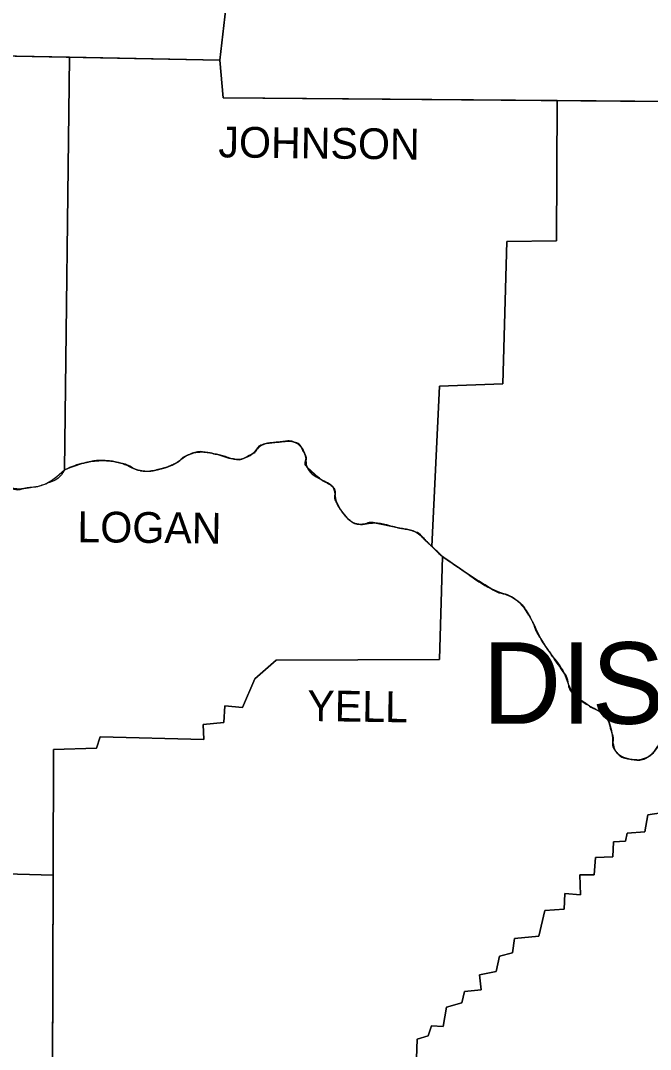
# Model space of a CAD drawing. Extents: x 1368042 to 1371376, y 380392 to 382637.
# Drawn here: x 1369334.7 to 1369518.4, y 381224.9 to 381525.2 of the extents above; entities that cross this region are included whole.
import ezdxf

# ---------------------------------------------------------------- set-up
doc = ezdxf.new("R2010")
doc.units = 0
doc.layers.add('Default', color=7, linetype='Continuous')
doc.layers.add('R_No Plot', color=7, linetype='Continuous')

msp = doc.modelspace()

# ---------------------------------------------------------------- linework, layer by layer
at = {"layer": 'Default'}
for points in [[(1369128.89, 381624.79), (1369168.7, 381624.58), (1369169.75, 381638.36), (1369184.15, 381638.36), (1369185.41, 381660.71), (1369266.85, 381657.78), (1369269.35, 381664.05), (1369302.97, 381664.26), (1369286.06, 381615.81), (1369282.72, 381538.34), (1369280.21, 381538.13), (1369278.96, 381514.74), (1369291.28, 381513.7), (1369293.16, 381515.58), (1369392.77, 381513.7), (1369393.81, 381502.63)], [(1369404.64, 381627.34), (1369405.51, 381615.6), (1369415.11, 381614.98), (1369412.61, 381579.89), (1369408.22, 381580.1), (1369407.39, 381574.47), (1369402.37, 381574.47), (1369402.17, 381564.86), (1369399.03, 381564.65), (1369397.99, 381552.33), (1369393.4, 381551.7), (1369392.77, 381532.91), (1369394.86, 381531.45), (1369392.77, 381513.7)], [(1369393.81, 381502.63), (1369625.61, 381500.75), (1369626.65, 381522.68), (1369681.07, 381522.05)], [(1369348.92, 381514.53), (1369347.45, 381394.05)], [(1369491.19, 381501.84), (1369490.97, 381460.94), (1369476.56, 381460.73), (1369475.31, 381419.17), (1369456.93, 381418.54), (1369454.66, 381371.69)], [(1369320.52, 381400.73), (1369319.05, 381370.87), (1369291.91, 381370.66), (1369290.45, 381343.51), (1369263.51, 381344.14), (1369262.67, 381316.16), (1369234.48, 381315.95), (1369233.65, 381287.97), (1369251.4, 381286.92), (1369250.77, 381278.36), (1369344.2, 381275.78)], [(1369457.71, 381368.78), (1369456.88, 381338.71), (1369409.27, 381338.5), (1369403, 381333.07), (1369399.45, 381324.72), (1369394.23, 381325.14), (1369394.02, 381320.33), (1369387.97, 381319.71), (1369388.18, 381315.32), (1369357.9, 381316.16), (1369356.85, 381312.82), (1369344.32, 381312.4), (1369344.2, 381275.78)], [(1369522.24, 381294.02), (1369517.65, 381293.4), (1369516.81, 381288.38), (1369511.59, 381287.97), (1369511.17, 381285.67), (1369507.62, 381285.46), (1369507.41, 381281.08), (1369502.4, 381280.87), (1369501.98, 381275.85), (1369497.81, 381275.85), (1369498.02, 381270.01), (1369493.42, 381270.43), (1369493.21, 381265.83), (1369487.58, 381265.41), (1369485.9, 381257.9), (1369478.8, 381257.27), (1369478.18, 381253.09), (1369474.42, 381252.05), (1369473.38, 381247.66), (1369468.57, 381246.62), (1369468.99, 381242.24), (1369464.19, 381241.82), (1369463.35, 381238.48), (1369458.97, 381237.22), (1369457.92, 381231.59), (1369454.58, 381231.79), (1369453.54, 381228.87), (1369450.4, 381227.83), (1369450.2, 381222.19)], [(1369344.2, 381275.78), (1369343.9, 381190.24), (1369333.46, 381190.03), (1369334.3, 381183.77), (1369324.27, 381183.97), (1369324.07, 381179.38), (1369314.25, 381179.38), (1369314.46, 381176.04), (1369299.84, 381175.62), (1369299.63, 381162.88), (1369285.43, 381164.14), (1369283.14, 381061.4), (1369202.74, 381061.61), (1369200.86, 381037.8), (1369203.78, 381035.71), (1369203.57, 381008.98), (1369143.36, 381011.63)]]:
    msp.add_lwpolyline(points, dxfattribs=at)
for points in [[(1369347.45, 381394.05), (1369354.35, 381396.34), (1369359.36, 381396.76), (1369364.37, 381395.93), (1369369.59, 381393.84), (1369375.23, 381394.26), (1369379.4, 381395.72), (1369383.58, 381398.43), (1369388.18, 381399.27), (1369392.56, 381398.43), (1369397.15, 381397.18), (1369402.17, 381398.64), (1369405.09, 381401.35), (1369410.1, 381402.19), (1369414.49, 381402.19), (1369417.62, 381398.64), (1369418.25, 381394.88), (1369422.21, 381391.33), (1369425.76, 381389.03), (1369426.81, 381384.65), (1369428.69, 381381.52), (1369430.57, 381379.43), (1369433.28, 381378.18), (1369437.88, 381378.59), (1369444.98, 381377.13), (1369449.57, 381376.09), (1369453.75, 381372.54), (1369457.71, 381368.78)], [(1369320.52, 381400.73), (1369325.11, 381397.81), (1369328.66, 381393), (1369331.79, 381389.03), (1369337.01, 381388.83), (1369341.19, 381389.66), (1369347.45, 381394.05)], [(1369457.71, 381368.78), (1369465.02, 381363.77), (1369471.91, 381359.38), (1369479.01, 381356.25), (1369482.98, 381351.66), (1369486.53, 381344.56), (1369489.45, 381340.17), (1369493.21, 381334.74), (1369495.93, 381328.69), (1369500.31, 381325.34), (1369504.91, 381322.42), (1369507.2, 381317.2), (1369508.25, 381311.98), (1369513.26, 381309.47), (1369518.06, 381310.52), (1369520.78, 381313.65), (1369523.28, 381319.08), (1369528.92, 381320.75), (1369536.23, 381321.38), (1369544.58, 381323.26), (1369553.77, 381322.84), (1369566.72, 381322)]]:
    msp.add_spline(points, degree=3, dxfattribs=at)
at = {"layer": 'R_No Plot'}
for p, q in [((1369347.45, 381394.05), (1369348.92, 381514.53)), ((1369348.92, 381514.53), (1369347.45, 381394.05)), ((1369348.92, 381514.53), (1369348.92, 381514.53)), ((1369348.92, 381514.53), (1369392.77, 381513.7)), ((1369392.77, 381513.7), (1369348.92, 381514.53)), ((1369392.77, 381513.7), (1369393.81, 381502.63)), ((1369393.81, 381502.63), (1369392.77, 381513.7)), ((1369393.81, 381502.63), (1369543.11, 381501.42)), ((1369491.19, 381501.84), (1369393.81, 381502.63)), ((1369491.19, 381501.84), (1369490.97, 381460.94)), ((1369543.11, 381501.42), (1369491.19, 381501.84)), ((1369476.56, 381460.73), (1369475.31, 381419.17)), ((1369490.97, 381460.94), (1369476.56, 381460.73)), ((1369456.93, 381418.54), (1369454.66, 381371.69)), ((1369475.31, 381419.17), (1369456.93, 381418.54)), ((1369387.98, 381399.29), (1369388.18, 381399.27)), ((1369368.84, 381394.03), (1369369.59, 381393.84)), ((1369418.25, 381394.88), (1369421.72, 381391.72)), ((1369430.57, 381379.43), (1369430.57, 381379.43)), ((1369433.28, 381378.18), (1369435.57, 381378.4)), ((1369437.88, 381378.59), (1369444.6, 381377.21)), ((1369482.98, 381351.66), (1369481.45, 381353.93)), ((1369394.23, 381325.14), (1369394.02, 381320.33)), ((1369504.91, 381322.42), (1369504.7, 381322.62)), ((1369394.02, 381320.33), (1369387.97, 381319.71)), ((1369357.9, 381316.16), (1369356.85, 381312.82)), ((1369344.32, 381312.4), (1369344.2, 381275.78)), ((1369356.85, 381312.82), (1369344.32, 381312.4)), ((1369344.2, 381275.78), (1369343.9, 381190.24)), ((1369493.42, 381270.43), (1369493.21, 381265.83)), ((1369498.02, 381270.01), (1369493.42, 381270.43)), ((1369468.57, 381246.62), (1369468.99, 381242.24)), ((1369464.19, 381241.82), (1369463.35, 381238.48)), ((1369468.99, 381242.24), (1369464.19, 381241.82))]:
    msp.add_line(p, q, dxfattribs=at)
for points in [[(1369302.97, 381664.26), (1369286.06, 381615.81), (1369282.72, 381538.34), (1369280.21, 381538.13), (1369278.99, 381515.39), (1369278.96, 381514.74), (1369291.28, 381513.7), (1369293.16, 381515.58), (1369348.92, 381514.53)], [(1369404.64, 381627.34), (1369405.51, 381615.6), (1369415.11, 381614.98), (1369412.61, 381579.89), (1369408.22, 381580.1), (1369407.39, 381574.47), (1369402.37, 381574.47), (1369402.17, 381564.86), (1369399.03, 381564.65), (1369397.99, 381552.33), (1369393.4, 381551.7), (1369392.77, 381532.91), (1369394.86, 381531.45), (1369392.77, 381513.7)], [(1369392.77, 381513.7), (1369394.86, 381531.45), (1369392.77, 381532.91), (1369393.4, 381551.7)], [(1369348.92, 381514.53), (1369348.92, 381514.53), (1369297.34, 381515.5)], [(1369348.92, 381514.53), (1369348.92, 381514.53)], [(1369454.66, 381371.69), (1369456.93, 381418.54), (1369475.31, 381419.17), (1369476.56, 381460.73), (1369490.97, 381460.94), (1369491.19, 381501.84)], [(1369454.66, 381371.69), (1369454.66, 381371.69)], [(1369344.2, 381275.78), (1369344.32, 381312.4), (1369356.85, 381312.82), (1369357.9, 381316.16), (1369388.18, 381315.32), (1369387.97, 381319.71), (1369394.02, 381320.33), (1369394.23, 381325.14), (1369399.45, 381324.72), (1369403, 381333.07), (1369409.27, 381338.5), (1369456.88, 381338.71), (1369457.71, 381368.78)], [(1369457.71, 381368.78), (1369456.88, 381338.71), (1369409.27, 381338.5), (1369403, 381333.07)], [(1369263.33, 381338.19), (1369262.67, 381316.16), (1369234.48, 381315.95), (1369233.65, 381287.97), (1369251.4, 381286.92), (1369250.77, 381278.36), (1369344.2, 381275.78)], [(1369403, 381333.07), (1369399.45, 381324.72), (1369394.23, 381325.14)], [(1369387.97, 381319.71), (1369388.18, 381315.32), (1369357.9, 381316.16)], [(1369344.2, 381275.78), (1369250.77, 381278.36), (1369251.4, 381286.92), (1369233.65, 381287.97), (1369234.16, 381305.13)], [(1369450.2, 381222.19), (1369450.4, 381227.83), (1369453.54, 381228.87), (1369454.58, 381231.79), (1369457.92, 381231.59), (1369458.97, 381237.22), (1369463.35, 381238.48), (1369464.19, 381241.82), (1369468.99, 381242.24), (1369468.57, 381246.62), (1369473.38, 381247.66), (1369474.42, 381252.05), (1369478.18, 381253.09), (1369478.8, 381257.27), (1369485.9, 381257.9), (1369487.58, 381265.41), (1369493.21, 381265.83), (1369493.42, 381270.43), (1369498.02, 381270.01), (1369497.81, 381275.85), (1369501.98, 381275.85), (1369502.4, 381280.87), (1369507.41, 381281.08), (1369507.62, 381285.46), (1369511.17, 381285.67), (1369511.59, 381287.97), (1369516.81, 381288.38), (1369517.65, 381293.4), (1369522.24, 381294.02)], [(1369522.24, 381294.24), (1369522.24, 381294.02), (1369517.65, 381293.4), (1369516.81, 381288.38)], [(1369516.81, 381288.38), (1369511.59, 381287.97), (1369511.17, 381285.67)], [(1369511.17, 381285.67), (1369507.62, 381285.46), (1369507.41, 381281.08), (1369502.4, 381280.87), (1369501.98, 381275.85)], [(1369501.98, 381275.85), (1369497.81, 381275.85), (1369498.02, 381270.01)], [(1369285.43, 381164.14), (1369299.63, 381162.88), (1369299.84, 381175.62), (1369314.46, 381176.04), (1369314.25, 381179.38), (1369324.07, 381179.38), (1369324.27, 381183.97), (1369334.3, 381183.77), (1369333.46, 381190.03), (1369343.9, 381190.24), (1369344.2, 381275.78)], [(1369493.21, 381265.83), (1369487.58, 381265.41), (1369485.9, 381257.9)], [(1369485.9, 381257.9), (1369478.8, 381257.27), (1369478.18, 381253.09), (1369474.42, 381252.05)], [(1369474.42, 381252.05), (1369473.38, 381247.66), (1369468.57, 381246.62)], [(1369463.35, 381238.48), (1369458.97, 381237.22), (1369457.92, 381231.59), (1369454.58, 381231.79), (1369453.54, 381228.87), (1369450.4, 381227.83), (1369450.2, 381222.19)]]:
    msp.add_lwpolyline(points, dxfattribs=at)
for points, degree in [([(1369457.71, 381368.78), (1369456.44, 381370.09), (1369455.08, 381371.29), (1369453.75, 381372.54), (1369452.41, 381373.79), (1369451.31, 381375.42), (1369449.57, 381376.09), (1369448.07, 381376.66), (1369446.51, 381376.8), (1369444.98, 381377.13), (1369442.61, 381377.64), (1369440.24, 381378.13), (1369437.88, 381378.59), (1369436.37, 381378.89), (1369434.8, 381377.94), (1369433.28, 381378.18), (1369432.29, 381378.33), (1369431.38, 381378.75), (1369430.57, 381379.43), (1369429.8, 381380.07), (1369429.25, 381380.74), (1369428.69, 381381.52), (1369427.96, 381382.52), (1369427.36, 381383.58), (1369426.81, 381384.65), (1369426.12, 381385.97), (1369426.8, 381387.88), (1369425.76, 381389.03), (1369424.79, 381390.11), (1369423.33, 381390.47), (1369422.21, 381391.33), (1369420.81, 381392.42), (1369419.4, 381393.5), (1369418.25, 381394.88), (1369417.42, 381395.87), (1369418.23, 381397.48), (1369417.62, 381398.64), (1369416.86, 381400.09), (1369416.05, 381401.71), (1369414.49, 381402.19), (1369413.04, 381402.64), (1369411.55, 381402.33), (1369410.1, 381402.19), (1369408.42, 381402.03), (1369406.74, 381401.89), (1369405.09, 381401.35), (1369403.8, 381400.94), (1369403.44, 381399.29), (1369402.17, 381398.64), (1369400.5, 381397.8), (1369398.83, 381396.87), (1369397.15, 381397.18), (1369395.62, 381397.46), (1369394.11, 381398.09), (1369392.56, 381398.43), (1369391.1, 381398.76), (1369389.64, 381399.08), (1369388.18, 381399.27), (1369386.65, 381399.46), (1369385.11, 381399.07), (1369383.58, 381398.43), (1369381.95, 381397.75), (1369380.92, 381396.41), (1369379.4, 381395.72), (1369378.05, 381395.1), (1369376.67, 381394.62), (1369375.23, 381394.26), (1369373.39, 381393.79), (1369371.41, 381393.51), (1369369.59, 381393.84), (1369367.78, 381394.16), (1369366.2, 381395.48), (1369364.37, 381395.93), (1369362.71, 381396.33), (1369361.04, 381396.68), (1369359.36, 381396.76), (1369357.69, 381396.84), (1369356.01, 381396.72), (1369354.35, 381396.34), (1369351.95, 381395.8), (1369349.68, 381395.08), (1369347.45, 381394.05)], 3), ([(1369403.63, 381400.09), (1369404.04, 381400.63), (1369404.45, 381401.15), (1369405.09, 381401.35), (1369406.74, 381401.89), (1369408.42, 381402.03), (1369410.1, 381402.19), (1369411.55, 381402.33), (1369413.04, 381402.64), (1369414.49, 381402.19)], 3), ([(1369414.49, 381402.19), (1369416.05, 381401.71), (1369416.86, 381400.09), (1369417.62, 381398.64)], 2), ([(1369383.58, 381398.43), (1369385.04, 381399.04), (1369386.52, 381399.43), (1369387.98, 381399.29)], 2), ([(1369388.18, 381399.27), (1369389.64, 381399.08), (1369391.1, 381398.76), (1369392.56, 381398.43), (1369393.88, 381398.14), (1369395.17, 381397.64), (1369396.46, 381397.33)], 3), ([(1369396.46, 381397.33), (1369396.69, 381397.27), (1369396.92, 381397.22), (1369397.15, 381397.18), (1369398.83, 381396.87), (1369400.5, 381397.8), (1369402.17, 381398.64), (1369402.81, 381398.97), (1369403.21, 381399.54), (1369403.63, 381400.09)], 3), ([(1369347.45, 381394.05), (1369349.68, 381395.08), (1369351.95, 381395.8), (1369354.35, 381396.34), (1369356.01, 381396.72), (1369357.69, 381396.84), (1369359.36, 381396.76), (1369361.04, 381396.68), (1369362.71, 381396.33), (1369364.37, 381395.93), (1369365.01, 381395.77), (1369365.62, 381395.51), (1369366.22, 381395.22)], 3), ([(1369379.4, 381395.72), (1369380.92, 381396.41), (1369381.95, 381397.75), (1369383.58, 381398.43)], 2), ([(1369417.62, 381398.64), (1369418.23, 381397.48), (1369417.42, 381395.87), (1369418.25, 381394.88)], 2), ([(1369347.45, 381394.05), (1369346.34, 381391.73), (1369343.67, 381390.56), (1369341.19, 381389.66), (1369339.81, 381389.16), (1369338.41, 381388.99), (1369337.01, 381388.83), (1369335.3, 381388.62), (1369333.25, 381387.77), (1369331.79, 381389.03)], 3), ([(1369366.22, 381395.22), (1369367.09, 381394.8), (1369367.94, 381394.32), (1369368.84, 381394.03)], 2), ([(1369369.59, 381393.84), (1369369.89, 381393.78), (1369370.2, 381393.75), (1369370.5, 381393.72)], 2), ([(1369370.5, 381393.72), (1369372.06, 381393.61), (1369373.69, 381393.87), (1369375.23, 381394.26)], 2), ([(1369375.23, 381394.26), (1369376.67, 381394.62), (1369378.05, 381395.1), (1369379.4, 381395.72)], 2), ([(1369421.72, 381391.72), (1369421.88, 381391.59), (1369422.05, 381391.46), (1369422.21, 381391.33)], 2), ([(1369422.21, 381391.33), (1369422.64, 381391), (1369423.11, 381390.75), (1369423.59, 381390.5)], 2), ([(1369423.59, 381390.5), (1369424.37, 381390.09), (1369425.16, 381389.7), (1369425.76, 381389.03), (1369426.8, 381387.88), (1369426.12, 381385.97), (1369426.81, 381384.65)], 3), ([(1369426.81, 381384.65), (1369427.36, 381383.58), (1369427.96, 381382.52), (1369428.69, 381381.52), (1369428.96, 381381.13), (1369429.24, 381380.77), (1369429.54, 381380.43)], 3), ([(1369429.54, 381380.43), (1369429.85, 381380.08), (1369430.18, 381379.75), (1369430.57, 381379.43)], 2), ([(1369430.57, 381379.43), (1369431.39, 381378.75), (1369432.29, 381378.33), (1369433.28, 381378.18)], 2), ([(1369435.57, 381378.4), (1369436.34, 381378.58), (1369437.12, 381378.74), (1369437.88, 381378.59)], 2), ([(1369444.6, 381377.21), (1369444.72, 381377.19), (1369444.85, 381377.16), (1369444.98, 381377.13), (1369446.51, 381376.8), (1369448.07, 381376.66), (1369449.57, 381376.09), (1369449.81, 381376), (1369450.04, 381375.89), (1369450.26, 381375.76)], 3), ([(1369450.26, 381375.76), (1369451.62, 381374.98), (1369452.59, 381373.61), (1369453.75, 381372.54), (1369454.05, 381372.25), (1369454.35, 381371.97), (1369454.66, 381371.69)], 3), ([(1369454.66, 381371.69), (1369455.69, 381370.74), (1369456.73, 381369.79), (1369457.71, 381368.78)], 2), ([(1369457.71, 381368.78), (1369460.14, 381367.1), (1369462.58, 381365.43), (1369465.02, 381363.77), (1369467.27, 381362.23), (1369469.6, 381360.82), (1369471.91, 381359.38), (1369474.11, 381358.02), (1369476.82, 381357.74), (1369479.01, 381356.25), (1369480.73, 381355.08), (1369481.95, 381353.42), (1369482.98, 381351.66), (1369484.32, 381349.34), (1369485.08, 381346.77), (1369486.53, 381344.56), (1369487.49, 381343.09), (1369488.47, 381341.63), (1369489.45, 381340.17), (1369490.69, 381338.35), (1369491.97, 381336.56), (1369493.21, 381334.74), (1369494.46, 381332.92), (1369494.37, 381330.32), (1369495.93, 381328.69), (1369497.23, 381327.33), (1369498.81, 381326.4), (1369500.31, 381325.34), (1369501.8, 381324.3), (1369503.53, 381323.75), (1369504.91, 381322.42), (1369506.35, 381321.03), (1369506.59, 381318.99), (1369507.2, 381317.2), (1369507.78, 381315.53), (1369507.02, 381313.64), (1369508.25, 381311.98), (1369509.55, 381310.24), (1369511.48, 381309.7), (1369513.26, 381309.47), (1369514.82, 381309.28), (1369516.6, 381309.45), (1369518.06, 381310.52), (1369519.3, 381311.42), (1369519.99, 381312.51), (1369520.78, 381313.65), (1369521.91, 381315.3), (1369521.52, 381317.81), (1369523.28, 381319.08), (1369525.02, 381320.33), (1369526.97, 381320.51), (1369528.92, 381320.75), (1369531.35, 381321.05), (1369533.83, 381321.03), (1369536.23, 381321.38), (1369539.04, 381321.79), (1369541.74, 381323.29), (1369544.58, 381323.26), (1369547.64, 381323.22), (1369550.71, 381323.03), (1369553.77, 381322.84), (1369558.09, 381322.57), (1369562.41, 381322.34), (1369566.72, 381322)], 3), ([(1369481.45, 381353.93), (1369480.76, 381354.81), (1369479.96, 381355.61), (1369479.01, 381356.25), (1369476.82, 381357.74), (1369474.11, 381358.02), (1369471.91, 381359.38), (1369469.6, 381360.82), (1369467.27, 381362.23), (1369465.02, 381363.77), (1369462.58, 381365.43), (1369460.14, 381367.1), (1369457.71, 381368.78)], 3), ([(1369486.53, 381344.56), (1369485.08, 381346.77), (1369484.32, 381349.34), (1369482.98, 381351.66)], 2), ([(1369493.21, 381334.74), (1369491.97, 381336.56), (1369490.69, 381338.35), (1369489.45, 381340.17), (1369488.47, 381341.63), (1369487.49, 381343.09), (1369486.53, 381344.56)], 3), ([(1369504.7, 381322.62), (1369503.35, 381323.81), (1369501.72, 381324.35), (1369500.31, 381325.34), (1369498.81, 381326.4), (1369497.23, 381327.33), (1369495.93, 381328.69), (1369494.37, 381330.32), (1369494.46, 381332.92), (1369493.21, 381334.74)], 3), ([(1369507.46, 381315.31), (1369507.44, 381315.95), (1369507.41, 381316.59), (1369507.2, 381317.2), (1369506.59, 381318.99), (1369506.35, 381321.03), (1369504.91, 381322.42)], 3), ([(1369512.34, 381309.62), (1369510.84, 381309.92), (1369509.33, 381310.54), (1369508.25, 381311.98), (1369507.47, 381313.03), (1369507.49, 381314.18), (1369507.46, 381315.31)], 3), ([(1369521.44, 381315.15), (1369521.28, 381314.61), (1369521.09, 381314.1), (1369520.78, 381313.65), (1369519.99, 381312.51), (1369519.3, 381311.42), (1369518.06, 381310.52), (1369517.96, 381310.45), (1369517.86, 381310.38), (1369517.76, 381310.31)], 3), ([(1369517.76, 381310.31), (1369516.36, 381309.43), (1369514.71, 381309.29), (1369513.26, 381309.47), (1369512.96, 381309.51), (1369512.65, 381309.56), (1369512.34, 381309.62)], 3)]:
    msp.add_open_spline(points, degree=degree, dxfattribs=at)
msp.add_spline([(1369320.52, 381400.73), (1369325.11, 381397.81), (1369328.66, 381393), (1369331.79, 381389.03), (1369337.01, 381388.83), (1369341.19, 381389.66), (1369347.45, 381394.05)], degree=3, dxfattribs=at)

# ---------------------------------------------------------------- texts
at = {"layer": 'Default'}
for s, rotation, p in [('JOHNSON', 359.3514, (1369392.35, 381485.3)), ('LOGAN', 359.3969, (1369351.21, 381372.96)), ('YELL', 359.1987, (1369418.25, 381320.75))]:
    msp.add_text(s, height=8.981, rotation=rotation, dxfattribs=at).set_placement(p)
msp.add_text('DISTRICT', height=23.805, dxfattribs=at).set_placement((1369469.41, 381319.92))

doc.saveas('drawing.dxf')
